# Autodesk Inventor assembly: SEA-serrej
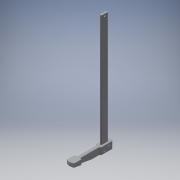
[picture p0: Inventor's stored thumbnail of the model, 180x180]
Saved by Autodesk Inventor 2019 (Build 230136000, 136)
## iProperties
Created: 2019-02
Part Number: SEA-serrej
Material: Générique
Document SubType Name: Assembly
Designer: si-nd67
Author: si-nd67
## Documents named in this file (4)
- E:\ECAM\serrejointsw\SEA-serrej.iam
- E:\ECAM\serrejointsw\Mors fixe14.ipt
- E:\ECAM\serrejointsw\branche14.ipt
- E:\ECAM\serrejointsw\GoupilleElast206-14.ipt
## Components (4 placed, 3 different names)
1. Mors fixe14:1 — Affleurement:1, Placage:1, Placage:2, Logement:1, Logement:2
2. branche14:1 — Affleurement:1, Placage:1, Placage:2
3. GoupilleElast206-14:1 — Logement:1
4. GoupilleElast206-14:2 — Logement:2
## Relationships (5: Mate 2, Insert 2, Flush 1)
- Affleurement:1 [Flush]: Mors fixe14:1 ↔ branche14:1
- Placage:1 [Mate]: Mors fixe14:1 ↔ branche14:1
- Placage:2 [Mate]: Mors fixe14:1 ↔ branche14:1
- Logement:1 [Insert]: Mors fixe14:1 ↔ GoupilleElast206-14:1
- Logement:2 [Insert]: Mors fixe14:1 ↔ GoupilleElast206-14:2
